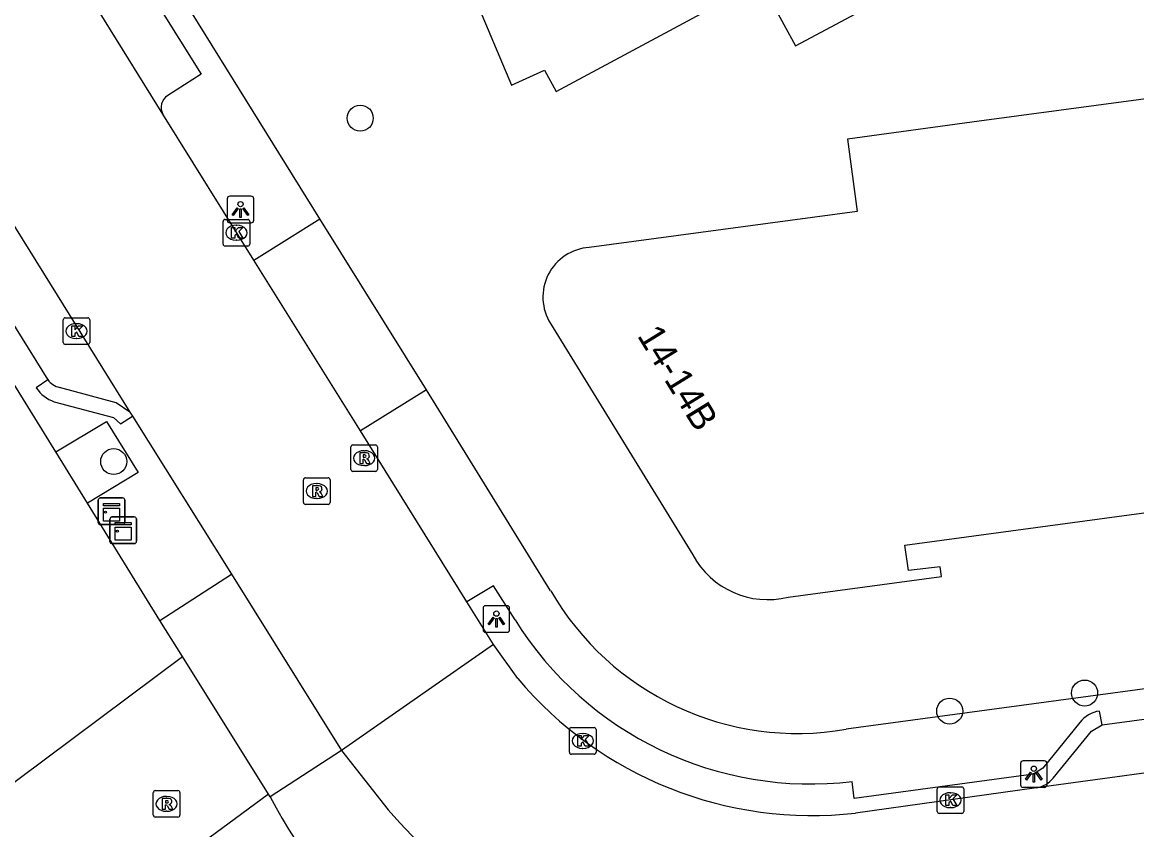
# Model space of a CAD drawing. Extents: x 158461 to 159795, y 387220 to 388672.
# Drawn here: x 158866.61 to 158908.52, y 387453.91 to 387484.26 of the extents above; entities that cross this region are included whole.
import ezdxf

# ---------------------------------------------------------------- set-up
doc = ezdxf.new("R2010")
doc.units = 0
for name, color, linetype in [('IMGEO_Boom', 7, 'Continuous'), ('IMGEO_Groenvoorziening', 7, 'Continuous'), ('IMGEO_Kast', 7, 'Continuous'), ('IMGEO_Kolk', 7, 'Continuous'), ('IMGEO_Lichtpunt', 7, 'Continuous'), ('IMGEO_Pand', 7, 'Continuous'), ('IMGEO_Pand_nummerreeks', 7, 'Continuous'), ('IMGEO_Rijbaan_lokaal_gesloten', 7, 'Continuous'), ('IMGEO_Rijbaan_lokaal_open', 7, 'Continuous'), ('IMGEO_Rioolput', 7, 'Continuous'), ('IMGEO_Voetpad_open', 7, 'Continuous')]:
    doc.layers.add(name, color=color, linetype=linetype)

msp = doc.modelspace()

# ---------------------------------------------------------------- linework, layer by layer
at = {"layer": 'IMGEO_Boom'}
for centre in [(158879.317, 387480.652), (158870.045, 387467.745), (158906.559, 387459.044), (158901.484, 387458.366)]:
    msp.add_circle(centre, 0.489, dxfattribs=at)
at = {"layer": 'IMGEO_Groenvoorziening'}
msp.add_lwpolyline([(158869.054, 387466.18), (158867.865, 387468.105)], dxfattribs=at)
at = {"layer": 'IMGEO_Kast'}
for p, q in [((158869.462, 387465.451), (158869.462, 387466.292)), ((158869.462, 387466.292), (158869.462, 387465.451)), ((158869.537, 387466.376), (158870.378, 387466.376)), ((158870.378, 387466.376), (158869.537, 387466.376)), ((158870.462, 387466.301), (158870.462, 387465.46)), ((158870.462, 387465.46), (158870.462, 387466.301)), ((158870.387, 387465.376), (158869.546, 387465.376)), ((158869.546, 387465.376), (158870.387, 387465.376)), ((158869.903, 387464.738), (158869.903, 387465.579)), ((158869.903, 387465.579), (158869.903, 387464.738)), ((158869.978, 387465.663), (158870.819, 387465.663)), ((158870.819, 387465.663), (158869.978, 387465.663)), ((158870.903, 387465.588), (158870.903, 387464.747)), ((158870.903, 387464.747), (158870.903, 387465.588)), ((158870.828, 387464.663), (158869.987, 387464.663)), ((158869.987, 387464.663), (158870.828, 387464.663))]:
    msp.add_line(p, q, dxfattribs=at)
for points in [[(158869.657, 387466.166), (158870.257, 387466.166), (158870.257, 387466.081), (158869.657, 387466.081), (158869.657, 387466.166)], [(158869.657, 387465.991), (158870.257, 387465.991), (158870.257, 387465.502), (158869.657, 387465.502), (158869.657, 387465.991)], [(158870.098, 387465.453), (158870.698, 387465.453), (158870.698, 387465.368), (158870.098, 387465.368), (158870.098, 387465.453)], [(158870.098, 387465.278), (158870.698, 387465.278), (158870.698, 387464.789), (158870.098, 387464.789), (158870.098, 387465.278)]]:
    msp.add_lwpolyline(points, dxfattribs=at)
for centre in [(158869.741, 387465.84), (158870.182, 387465.127)]:
    msp.add_circle(centre, 0.0377, dxfattribs=at)
for centre, start, end in [((158869.54, 387466.298), 92.4484, 184.2845), ((158869.54, 387466.298), 92.4484, 184.2845), ((158870.384, 387466.298), 2.4484, 94.2845), ((158870.384, 387466.298), 2.4484, 94.2845), ((158869.54, 387465.454), 182.4484, 274.2845), ((158869.54, 387465.454), 182.4484, 274.2845), ((158869.981, 387465.585), 92.4484, 184.2845), ((158869.981, 387465.585), 92.4484, 184.2845), ((158870.384, 387465.454), 272.4484, 4.2845), ((158870.384, 387465.454), 272.4484, 4.2845), ((158870.825, 387465.585), 2.4484, 94.2845), ((158870.825, 387465.585), 2.4484, 94.2845), ((158869.981, 387464.741), 182.4484, 274.2845), ((158869.981, 387464.741), 182.4484, 274.2845), ((158870.825, 387464.741), 272.4484, 4.2845), ((158870.825, 387464.741), 272.4484, 4.2845)]:
    msp.add_arc(centre, 0.0779, start, end, dxfattribs=at)
at = {"layer": 'IMGEO_Kolk'}
for p, q in [((158874.159, 387475.92), (158874.159, 387476.772)), ((158874.234, 387476.846), (158875.086, 387476.846)), ((158875.16, 387476.772), (158875.16, 387475.92)), ((158874.647, 387476.626), (158874.672, 387476.626)), ((158875.086, 387475.846), (158874.234, 387475.846)), ((158874.67, 387476.066), (158874.645, 387476.066)), ((158868.145, 387472.222), (158868.145, 387473.074)), ((158868.22, 387473.148), (158869.072, 387473.148)), ((158868.633, 387472.928), (158868.658, 387472.928)), ((158869.146, 387473.074), (158869.146, 387472.222)), ((158869.072, 387472.148), (158868.22, 387472.148)), ((158868.656, 387472.368), (158868.631, 387472.368)), ((158887.182, 387456.819), (158887.182, 387457.671)), ((158887.257, 387457.745), (158888.109, 387457.745)), ((158887.67, 387457.525), (158887.695, 387457.525)), ((158888.183, 387457.671), (158888.183, 387456.819)), ((158887.693, 387456.965), (158887.668, 387456.965)), ((158888.109, 387456.745), (158887.257, 387456.745)), ((158901.014, 387454.591), (158901.014, 387455.443)), ((158901.089, 387455.517), (158901.941, 387455.517)), ((158901.502, 387455.297), (158901.527, 387455.297)), ((158902.015, 387455.443), (158902.015, 387454.591)), ((158901.941, 387454.517), (158901.089, 387454.517)), ((158901.525, 387454.737), (158901.5, 387454.737))]:
    msp.add_line(p, q, dxfattribs=at)
for points in [[(158874.159, 387475.92), (158874.159, 387476.772)], [(158874.234, 387476.846), (158875.086, 387476.846)], [(158875.16, 387476.772), (158875.16, 387475.92)], [(158874.48, 387476.546), (158874.603, 387476.546), (158874.603, 387476.395), (158874.733, 387476.546), (158874.897, 387476.546), (158874.751, 387476.395), (158874.904, 387476.146), (158874.752, 387476.146), (158874.667, 387476.31), (158874.603, 387476.243), (158874.603, 387476.146), (158874.48, 387476.146), (158874.48, 387476.546)], [(158875.086, 387475.846), (158874.234, 387475.846)], [(158868.145, 387472.222), (158868.145, 387473.074)], [(158868.22, 387473.148), (158869.072, 387473.148)], [(158869.146, 387473.074), (158869.146, 387472.222)], [(158868.466, 387472.848), (158868.589, 387472.848), (158868.589, 387472.697), (158868.719, 387472.848), (158868.883, 387472.848), (158868.737, 387472.697), (158868.89, 387472.448), (158868.738, 387472.448), (158868.653, 387472.612), (158868.589, 387472.545), (158868.589, 387472.448), (158868.466, 387472.448), (158868.466, 387472.848)], [(158869.072, 387472.148), (158868.22, 387472.148)], [(158887.182, 387456.819), (158887.182, 387457.671)], [(158887.257, 387457.745), (158888.109, 387457.745)], [(158887.503, 387457.445), (158887.626, 387457.445), (158887.626, 387457.294), (158887.756, 387457.445), (158887.92, 387457.445), (158887.774, 387457.294), (158887.927, 387457.045), (158887.775, 387457.045), (158887.69, 387457.209), (158887.626, 387457.142), (158887.626, 387457.045), (158887.503, 387457.045), (158887.503, 387457.445)], [(158888.183, 387457.671), (158888.183, 387456.819)], [(158888.109, 387456.745), (158887.257, 387456.745)], [(158901.014, 387454.591), (158901.014, 387455.443)], [(158901.089, 387455.517), (158901.941, 387455.517)], [(158902.015, 387455.443), (158902.015, 387454.591)], [(158901.335, 387455.217), (158901.458, 387455.217), (158901.458, 387455.066), (158901.588, 387455.217), (158901.752, 387455.217), (158901.606, 387455.066), (158901.759, 387454.817), (158901.607, 387454.817), (158901.522, 387454.981), (158901.458, 387454.914), (158901.458, 387454.817), (158901.335, 387454.817), (158901.335, 387455.217)], [(158901.941, 387454.517), (158901.089, 387454.517)]]:
    msp.add_lwpolyline(points, dxfattribs=at)
for centre, start, end in [((158874.236, 387476.77), 91.552, 178.448), ((158874.236, 387476.77), 91.552, 178.448), ((158875.084, 387476.77), 1.552, 88.448), ((158875.084, 387476.77), 1.552, 88.448), ((158874.236, 387475.922), 181.552, 268.448), ((158874.236, 387475.922), 181.552, 268.448), ((158875.084, 387475.922), 271.552, 358.448), ((158875.084, 387475.922), 271.552, 358.448), ((158868.222, 387473.072), 91.552, 178.448), ((158868.222, 387473.072), 91.552, 178.448), ((158869.07, 387473.072), 1.552, 88.448), ((158869.07, 387473.072), 1.552, 88.448), ((158868.222, 387472.224), 181.552, 268.448), ((158868.222, 387472.224), 181.552, 268.448), ((158869.07, 387472.224), 271.552, 358.448), ((158869.07, 387472.224), 271.552, 358.448), ((158887.259, 387457.669), 91.552, 178.448), ((158887.259, 387457.669), 91.552, 178.448), ((158888.107, 387457.669), 1.552, 88.448), ((158888.107, 387457.669), 1.552, 88.448), ((158887.259, 387456.821), 181.552, 268.448), ((158887.259, 387456.821), 181.552, 268.448), ((158888.107, 387456.821), 271.552, 358.448), ((158888.107, 387456.821), 271.552, 358.448), ((158901.091, 387455.441), 91.552, 178.448), ((158901.091, 387455.441), 91.552, 178.448), ((158901.939, 387455.441), 1.552, 88.448), ((158901.939, 387455.441), 1.552, 88.448), ((158901.091, 387454.593), 181.552, 268.448), ((158901.091, 387454.593), 181.552, 268.448), ((158901.939, 387454.593), 271.552, 358.448), ((158901.939, 387454.593), 271.552, 358.448)]:
    msp.add_arc(centre, 0.0765, start, end, dxfattribs=at)
for centre, major_axis, ratio, start_param, end_param in [((158874.646, 387476.346), (-0.387, 0.002), 0.722429, 4.712389, 7.853982), ((158874.671, 387476.346), (-0.39, 0.002), 0.717154, 1.570796, 4.712389), ((158868.632, 387472.648), (-0.387, 0.002), 0.722429, 4.712389, 7.853982), ((158868.657, 387472.648), (-0.39, 0.002), 0.717154, 1.570796, 4.712389), ((158887.669, 387457.245), (-0.387, 0.002), 0.722429, 4.712389, 7.853982), ((158887.694, 387457.245), (-0.39, 0.002), 0.717154, 1.570796, 4.712389), ((158901.501, 387455.017), (-0.387, 0.002), 0.722429, 4.712389, 7.853982), ((158901.526, 387455.017), (-0.39, 0.002), 0.717154, 1.570796, 4.712389)]:
    msp.add_ellipse(centre, major_axis=major_axis, ratio=ratio, start_param=start_param, end_param=end_param, dxfattribs=at)
at = {"layer": 'IMGEO_Lichtpunt'}
for p, q in [((158874.316, 387477.623), (158874.316, 387476.816)), ((158874.316, 387477.623), (158874.316, 387476.816)), ((158875.218, 387477.718), (158874.41, 387477.718)), ((158875.218, 387477.718), (158874.41, 387477.718)), ((158875.312, 387476.816), (158875.312, 387477.623)), ((158875.312, 387476.816), (158875.312, 387477.623)), ((158874.41, 387476.722), (158875.218, 387476.722)), ((158874.41, 387476.722), (158875.218, 387476.722)), ((158883.937, 387462.232), (158883.937, 387461.425)), ((158883.937, 387462.232), (158883.937, 387461.425)), ((158884.839, 387462.327), (158884.031, 387462.327)), ((158884.839, 387462.327), (158884.031, 387462.327)), ((158884.933, 387461.425), (158884.933, 387462.232)), ((158884.933, 387461.425), (158884.933, 387462.232)), ((158884.031, 387461.331), (158884.839, 387461.331)), ((158884.031, 387461.331), (158884.839, 387461.331)), ((158904.149, 387456.401), (158904.149, 387455.594)), ((158904.149, 387456.401), (158904.149, 387455.594)), ((158905.051, 387456.496), (158904.243, 387456.496)), ((158905.051, 387456.496), (158904.243, 387456.496)), ((158905.145, 387455.594), (158905.145, 387456.401)), ((158905.145, 387455.594), (158905.145, 387456.401)), ((158904.243, 387455.5), (158905.051, 387455.5)), ((158904.243, 387455.5), (158905.051, 387455.5))]:
    msp.add_line(p, q, dxfattribs=at)
for points in [[(158874.69, 387477.287), (158874.729, 387477.259), (158874.541, 387476.997), (158874.503, 387477.024), (158874.69, 387477.287)], [(158874.792, 387477.239), (158874.839, 387477.239), (158874.839, 387476.917), (158874.792, 387476.917), (158874.792, 387477.239)], [(158874.902, 387477.259), (158874.94, 387477.286), (158875.127, 387477.024), (158875.088, 387476.996), (158874.902, 387477.259)], [(158884.311, 387461.896), (158884.35, 387461.868), (158884.162, 387461.606), (158884.124, 387461.633), (158884.311, 387461.896)], [(158884.413, 387461.848), (158884.46, 387461.848), (158884.46, 387461.526), (158884.413, 387461.526), (158884.413, 387461.848)], [(158884.523, 387461.868), (158884.561, 387461.895), (158884.748, 387461.633), (158884.709, 387461.605), (158884.523, 387461.868)], [(158904.523, 387456.065), (158904.562, 387456.037), (158904.374, 387455.775), (158904.336, 387455.802), (158904.523, 387456.065)], [(158904.625, 387456.017), (158904.672, 387456.017), (158904.672, 387455.695), (158904.625, 387455.695), (158904.625, 387456.017)], [(158904.735, 387456.037), (158904.773, 387456.064), (158904.96, 387455.802), (158904.921, 387455.774), (158904.735, 387456.037)]]:
    msp.add_lwpolyline(points, dxfattribs=at)
for centre in [(158874.815, 387477.421), (158884.436, 387462.03), (158904.648, 387456.199)]:
    msp.add_circle(centre, 0.0994, dxfattribs=at)
for centre, start, end in [((158874.41, 387477.623), 90, 180), ((158874.41, 387477.623), 90, 180), ((158875.218, 387477.623), 0, 90), ((158875.218, 387477.623), 0, 90), ((158874.41, 387476.816), 180, 270), ((158874.41, 387476.816), 180, 270), ((158875.218, 387476.816), 270, 0), ((158875.218, 387476.816), 270, 360), ((158884.031, 387462.232), 90, 180), ((158884.031, 387462.232), 90, 180), ((158884.839, 387462.232), 0, 90), ((158884.839, 387462.232), 0, 90), ((158884.031, 387461.425), 180, 270), ((158884.031, 387461.425), 180, 270), ((158884.839, 387461.425), 270, 0), ((158884.839, 387461.425), 270, 360), ((158904.243, 387456.401), 90, 180), ((158904.243, 387456.401), 90, 180), ((158905.051, 387456.401), 0, 90), ((158905.051, 387456.401), 0, 90), ((158904.243, 387455.594), 180, 270), ((158904.243, 387455.594), 180, 270), ((158905.051, 387455.594), 270, 0), ((158905.051, 387455.594), 270, 360)]:
    msp.add_arc(centre, 0.0946, start, end, dxfattribs=at)
at = {"layer": 'IMGEO_Pand'}
for points in [[(158918.572, 387540.133), (158901.241, 387530.775), (158903.617, 387526.376), (158911.389, 387511.996), (158889.122, 387500), (158883.251, 387496.837), (158878.849, 387494.465), (158881.717, 387489.193), (158881.89, 387489.276), (158885, 387481.898), (158886.246, 387482.453), (158886.683, 387481.656), (158894.367, 387485.79), (158895.687, 387483.369), (158900.055, 387485.717)], [(158895.408, 387462.651), (158901.178, 387463.425), (158901.123, 387463.789), (158899.932, 387463.646), (158899.801, 387464.599), (158923.909, 387467.857), (158924.084, 387466.503), (158930.889, 387467.446), (158928.491, 387471.834), (158922.735, 387482.364), (158922.527, 387482.333), (158922.456, 387483.206), (158917.386, 387482.524), (158902.592, 387480.534), (158897.636, 387479.867), (158898, 387477.138), (158887.928, 387475.792)], [(158886.476, 387472.928), (158891.823, 387464.24)]]:
    msp.add_lwpolyline(points, dxfattribs=at)
for centre, radius, start, end in [((158888.053, 387473.929), 1.867, 93.8291, 212.4024), ((158894.636, 387465.748), 3.192, 208.1996, 283.9912)]:
    msp.add_arc(centre, radius, start, end, dxfattribs=at)
at = {"layer": 'IMGEO_Rijbaan_lokaal_gesloten'}
for points in [[(158846.014, 387509.226), (158870.648, 387469.607)], [(158871.89, 387480.802), (158867.506, 387487.881)], [(158875.318, 387475.314), (158871.89, 387480.802)], [(158879.331, 387468.895), (158875.318, 387475.314)], [(158870.648, 387469.607), (158870.748, 387469.446)], [(158870.748, 387469.446), (158874.475, 387463.509)], [(158883.328, 387462.471), (158879.331, 387468.895)], [(158874.475, 387463.509), (158878.61, 387456.886)], [(158884.328, 387460.865), (158883.328, 387462.471)], [(158884.328, 387460.865), (158878.61, 387456.886)], [(158885.238, 387459.589), (158884.328, 387460.865)], [(158878.61, 387456.886), (158880.363, 387454.65)], [(158911.727, 387456.43), (158904.755, 387455.484)], [(158904.755, 387455.484), (158897.945, 387454.534)]]:
    msp.add_lwpolyline(points, dxfattribs=at)
for centre, radius, start, end in [((158896.307, 387468.915), 14.474, 220.1146, 276.4989), ((158895.992, 387468.359), 20.79, 221.2558, 278.1232)]:
    msp.add_arc(centre, radius, start, end, dxfattribs=at)
at = {"layer": 'IMGEO_Rijbaan_lokaal_open'}
for points in [[(158817.674, 387419.378), (158827.832, 387426.967), (158834.448, 387431.91), (158853.054, 387445.81), (158872.628, 387460.413)], [(158875.861, 387455.245), (158872.628, 387460.413)], [(158875.861, 387455.245), (158872.617, 387452.848)]]:
    msp.add_lwpolyline(points, dxfattribs=at)
at = {"layer": 'IMGEO_Rioolput'}
for p, q in [((158878.963, 387467.447), (158878.963, 387468.299)), ((158879.038, 387468.373), (158879.89, 387468.373)), ((158879.964, 387468.299), (158879.964, 387467.447)), ((158879.451, 387468.153), (158879.476, 387468.153)), ((158879.474, 387467.593), (158879.449, 387467.593)), ((158877.182, 387466.209), (158877.182, 387467.061)), ((158877.257, 387467.135), (158878.109, 387467.135)), ((158878.183, 387467.061), (158878.183, 387466.209)), ((158879.89, 387467.373), (158879.038, 387467.373)), ((158877.67, 387466.915), (158877.695, 387466.915)), ((158877.693, 387466.355), (158877.668, 387466.355)), ((158878.109, 387466.135), (158877.257, 387466.135)), ((158871.535, 387454.453), (158871.535, 387455.305)), ((158871.61, 387455.379), (158872.462, 387455.379)), ((158872.536, 387455.305), (158872.536, 387454.453)), ((158872.023, 387455.159), (158872.048, 387455.159)), ((158872.046, 387454.599), (158872.021, 387454.599)), ((158872.462, 387454.379), (158871.61, 387454.379))]:
    msp.add_line(p, q, dxfattribs=at)
for points in [[(158878.963, 387467.447), (158878.963, 387468.299)], [(158879.038, 387468.373), (158879.89, 387468.373)], [(158879.964, 387468.299), (158879.964, 387467.447)], [(158879.552, 387468.071), (158879.3, 387468.073), (158879.3, 387467.673)], [(158879.478, 387467.992), (158879.424, 387467.992), (158879.424, 387467.911)], [(158879.424, 387467.911), (158879.476, 387467.911)], [(158879.3, 387467.673), (158879.424, 387467.673), (158879.424, 387467.835), (158879.435, 387467.835)], [(158879.482, 387467.806), (158879.553, 387467.673), (158879.693, 387467.673), (158879.628, 387467.799)], [(158877.182, 387466.209), (158877.182, 387467.061)], [(158877.257, 387467.135), (158878.109, 387467.135)], [(158878.183, 387467.061), (158878.183, 387466.209)], [(158879.89, 387467.373), (158879.038, 387467.373)], [(158877.771, 387466.833), (158877.519, 387466.835), (158877.519, 387466.435)], [(158877.519, 387466.435), (158877.643, 387466.435), (158877.643, 387466.597), (158877.654, 387466.597)], [(158877.697, 387466.754), (158877.643, 387466.754), (158877.643, 387466.673)], [(158877.643, 387466.673), (158877.695, 387466.673)], [(158877.701, 387466.568), (158877.772, 387466.435), (158877.912, 387466.435), (158877.847, 387466.561)], [(158878.109, 387466.135), (158877.257, 387466.135)], [(158871.535, 387454.453), (158871.535, 387455.305)], [(158871.61, 387455.379), (158872.462, 387455.379)], [(158872.536, 387455.305), (158872.536, 387454.453)], [(158872.124, 387455.077), (158871.872, 387455.079), (158871.872, 387454.679)], [(158872.05, 387454.998), (158871.996, 387454.998), (158871.996, 387454.917)], [(158871.996, 387454.917), (158872.048, 387454.917)], [(158871.872, 387454.679), (158871.996, 387454.679), (158871.996, 387454.841), (158872.007, 387454.841)], [(158872.054, 387454.812), (158872.125, 387454.679), (158872.265, 387454.679), (158872.2, 387454.805)], [(158872.462, 387454.379), (158871.61, 387454.379)]]:
    msp.add_lwpolyline(points, dxfattribs=at)
for centre, radius, start, end in [((158879.04, 387468.297), 0.0765, 91.552, 178.448), ((158879.04, 387468.297), 0.0765, 91.552, 178.448), ((158879.888, 387468.297), 0.0765, 1.552, 88.448), ((158879.888, 387468.297), 0.0765, 1.552, 88.448), ((158879.46, 387468.1), 0.19, 274.7715, 282.9687), ((158879.484, 387467.896), 0.0964, 77.0061, 93.1865), ((158879.498, 387467.953), 0.0378, 276.6634, 79.6772), ((158879.551, 387467.961), 0.109, 350.3612, 89.416), ((158879.549, 387467.961), 0.112, 277.5842, 350.9817), ((158879.04, 387467.449), 0.0765, 181.552, 268.448), ((158879.04, 387467.449), 0.0765, 181.552, 268.448), ((158879.434, 387467.782), 0.0533, 26.0293, 88.6989), ((158879.533, 387467.746), 0.108, 29.5134, 73.7905), ((158879.888, 387467.449), 0.0765, 271.552, 358.448), ((158879.888, 387467.449), 0.0765, 271.552, 358.448), ((158877.259, 387467.059), 0.0765, 91.552, 178.448), ((158877.259, 387467.059), 0.0765, 91.552, 178.448), ((158878.107, 387467.059), 0.0765, 1.552, 88.448), ((158878.107, 387467.059), 0.0765, 1.552, 88.448), ((158877.653, 387466.544), 0.0533, 26.0293, 88.6989), ((158877.679, 387466.862), 0.19, 274.7715, 282.9687), ((158877.703, 387466.658), 0.0964, 77.0061, 93.1865), ((158877.717, 387466.715), 0.0378, 276.6634, 79.6772), ((158877.77, 387466.723), 0.109, 350.3612, 89.416), ((158877.768, 387466.723), 0.112, 277.5842, 350.9817), ((158877.752, 387466.508), 0.108, 29.5134, 73.7905), ((158877.259, 387466.211), 0.0765, 181.552, 268.448), ((158877.259, 387466.211), 0.0765, 181.552, 268.448), ((158878.107, 387466.211), 0.0765, 271.552, 358.448), ((158878.107, 387466.211), 0.0765, 271.552, 358.448), ((158871.612, 387455.303), 0.0765, 91.552, 178.448), ((158871.612, 387455.303), 0.0765, 91.552, 178.448), ((158872.46, 387455.303), 0.0765, 1.552, 88.448), ((158872.46, 387455.303), 0.0765, 1.552, 88.448), ((158872.032, 387455.106), 0.19, 274.7715, 282.9687), ((158872.056, 387454.902), 0.0964, 77.0061, 93.1865), ((158872.07, 387454.959), 0.0378, 276.6634, 79.6772), ((158872.123, 387454.967), 0.109, 350.3612, 89.416), ((158872.121, 387454.967), 0.112, 277.5842, 350.9817), ((158871.612, 387454.455), 0.0765, 181.552, 268.448), ((158871.612, 387454.455), 0.0765, 181.552, 268.448), ((158872.006, 387454.788), 0.0533, 26.0293, 88.6989), ((158872.105, 387454.752), 0.108, 29.5134, 73.7905), ((158872.46, 387454.455), 0.0765, 271.552, 358.448), ((158872.46, 387454.455), 0.0765, 271.552, 358.448)]:
    msp.add_arc(centre, radius, start, end, dxfattribs=at)
for centre, major_axis, ratio, start_param, end_param in [((158879.45, 387467.873), (-0.387, 0.002), 0.722429, 4.712389, 7.853982), ((158879.475, 387467.873), (-0.39, 0.002), 0.717154, 1.570796, 4.712389), ((158877.669, 387466.635), (-0.387, 0.002), 0.722429, 4.712389, 7.853982), ((158877.694, 387466.635), (-0.39, 0.002), 0.717154, 1.570796, 4.712389), ((158872.022, 387454.879), (-0.387, 0.002), 0.722429, 4.712389, 7.853982), ((158872.047, 387454.879), (-0.39, 0.002), 0.717154, 1.570796, 4.712389)]:
    msp.add_ellipse(centre, major_axis=major_axis, ratio=ratio, start_param=start_param, end_param=end_param, dxfattribs=at)
at = {"layer": 'IMGEO_Voetpad_open'}
for points in [[(158867.865, 387468.105), (158855.534, 387488.061), (158855.344, 387488.369), (158855.598, 387488.53), (158843.07, 387508.642), (158842.309, 387509.96), (158841.704, 387511.33), (158840.764, 387514.306)], [(158852.135, 387495.652), (158867.569, 387470.823)], [(158877.792, 387476.863), (158869.993, 387489.451)], [(158869.196, 387488.923), (158873.336, 387482.31), (158872.076, 387481.503)], [(158875.318, 387475.314), (158877.792, 387476.863)], [(158881.804, 387470.44), (158877.792, 387476.863)], [(158867.569, 387470.823), (158867.135, 387470.511)], [(158870.648, 387469.607), (158870.141, 387469.958), (158868.005, 387470.531)], [(158881.804, 387470.44), (158879.331, 387468.895)], [(158886.478, 387462.89), (158881.804, 387470.44)], [(158867.805, 387469.996), (158870.033, 387469.406), (158870.295, 387469.159), (158870.748, 387469.446)], [(158867.865, 387468.105), (158869.78, 387469.254), (158870.966, 387467.333), (158869.054, 387466.18)], [(158871.776, 387461.775), (158869.054, 387466.18)], [(158871.776, 387461.775), (158874.475, 387463.509)], [(158885.14, 387461.796), (158884.334, 387463.078), (158883.328, 387462.471)], [(158930.651, 387462.152), (158897.588, 387457.682)], [(158872.628, 387460.413), (158871.776, 387461.775)], [(158907.215, 387457.847), (158928.046, 387460.65)], [(158907.215, 387457.847), (158907.116, 387458.366)], [(158906.383, 387457.942), (158904.993, 387456.219), (158904.642, 387455.998), (158897.89, 387455.078), (158897.822, 387455.721)], [(158905.375, 387455.847), (158906.813, 387457.615), (158907.215, 387457.847)], [(158878.61, 387456.886), (158875.925, 387455.143)], [(158875.925, 387455.143), (158875.861, 387455.245)]]:
    msp.add_lwpolyline(points, dxfattribs=at)
for centre, radius, start, end in [((158872.367, 387481.051), 0.538, 122.7668, 207.5129), ((158868.152, 387471.223), 0.707, 214.4089, 257.9687), ((158868.215, 387471.222), 1.293, 213.3746, 251.5296), ((158895.766, 387468.249), 10.723, 209.9835, 279.7853), ((158896.251, 387468.717), 13.09, 211.9166, 276.8922), ((158907.269, 387457.256), 1.12, 97.8376, 142.2565), ((158904.6, 387456.459), 0.987, 279.0141, 321.6824), ((158895.756, 387465.7), 22.466, 208.0279, 282.052)]:
    msp.add_arc(centre, radius, start, end, dxfattribs=at)

# ---------------------------------------------------------------- texts
at = {"layer": 'IMGEO_Pand_nummerreeks'}
msp.add_text('14-14B', height=1, rotation=301.6101, dxfattribs=at).set_placement((158889.711, 387472.479))

doc.saveas('drawing.dxf')
